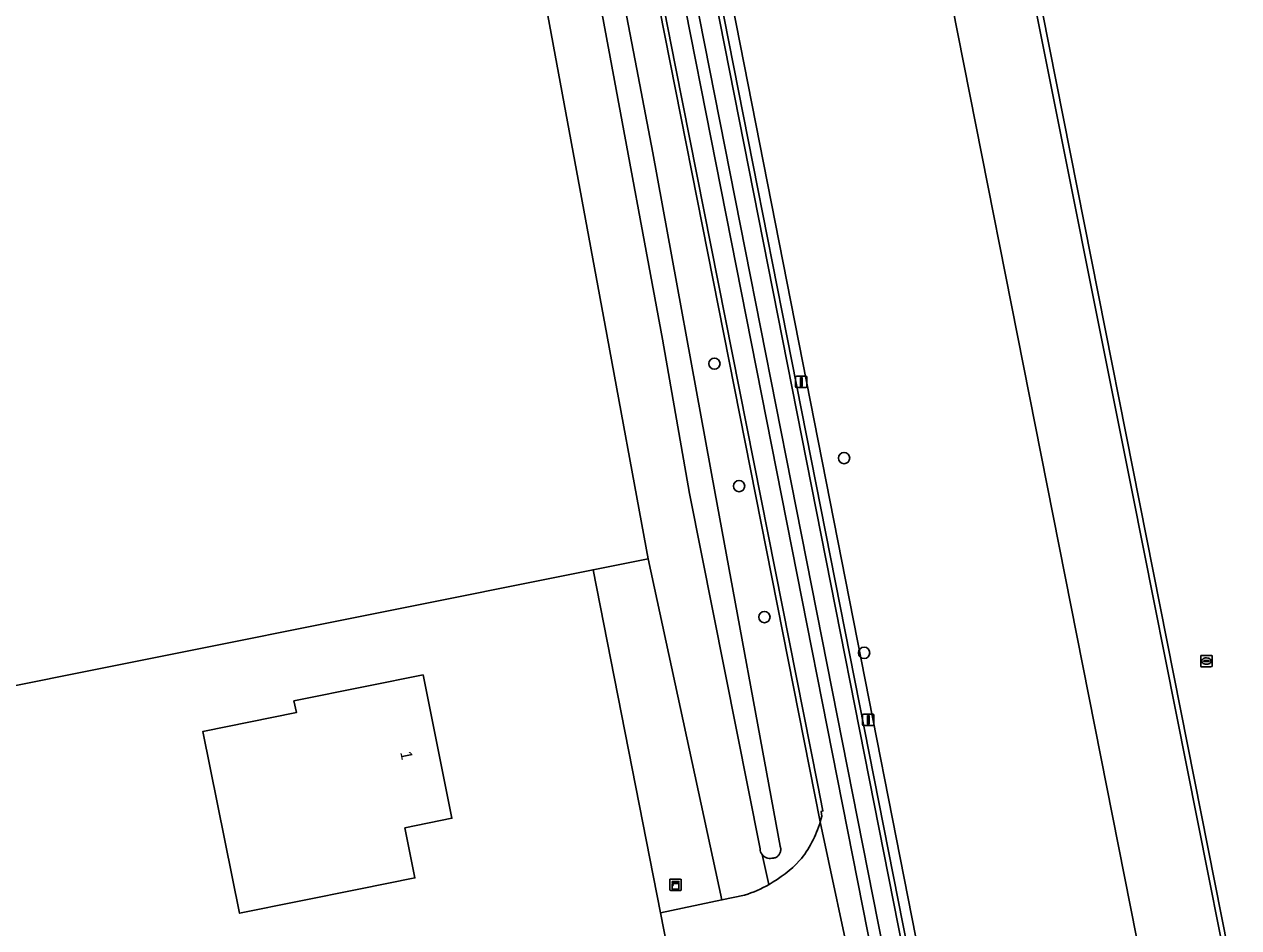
# Model space of a CAD drawing. Extents: x 160203 to 161530, y 379528 to 381797.
# Drawn here: x 160889.3 to 160995.1, y 379712.2 to 379790.9 of the extents above; entities that cross this region are included whole.
import ezdxf

# ---------------------------------------------------------------- set-up
doc = ezdxf.new("R2010")
doc.units = 0
for name, color, linetype in [('IMGEO_Berm_groen', 7, 'Continuous'), ('IMGEO_Berm_open', 7, 'Continuous'), ('IMGEO_Boom', 7, 'Continuous'), ('IMGEO_Erf', 7, 'Continuous'), ('IMGEO_Grasland_overig', 7, 'Continuous'), ('IMGEO_Groenvoorziening', 7, 'Continuous'), ('IMGEO_Hek', 7, 'Continuous'), ('IMGEO_Kast', 7, 'Continuous'), ('IMGEO_Lichtmast', 7, 'Continuous'), ('IMGEO_Loofbos', 7, 'Continuous'), ('IMGEO_Pand', 7, 'Continuous'), ('IMGEO_Pand_nummerreeks', 7, 'Continuous'), ('IMGEO_Rijbaan_lokaal_gesloten', 7, 'Continuous'), ('IMGEO_Rijbaan_lokaal_open', 7, 'Continuous'), ('IMGEO_Waterleidingput', 7, 'Continuous'), ('IMGEO_Waterloop', 7, 'Continuous')]:
    doc.layers.add(name, color=color, linetype=linetype)

msp = doc.modelspace()

# ---------------------------------------------------------------- linework, layer by layer
at = {"layer": 'IMGEO_Berm_groen'}
for points in [[(160958.63, 379721.42), (160935.77, 379837.08), (160928.05, 379876.62)], [(160928.2, 379862.18), (160942.76, 379786.36), (160944.04, 379779.68), (160949.49, 379750), (160955.13, 379719.31), (160955.14, 379719.29), (160955.16, 379719.23), (160955.18, 379719.16), (160955.19, 379719.09), (160955.19, 379719.03), (160955.19, 379718.96), (160955.18, 379718.89), (160955.17, 379718.82), (160955.15, 379718.76), (160955.12, 379718.7), (160955.09, 379718.64), (160955.06, 379718.58), (160955.02, 379718.53), (160954.97, 379718.48), (160954.92, 379718.43), (160954.87, 379718.39), (160954.81, 379718.35), (160954.75, 379718.32), (160954.69, 379718.3), (160954.62, 379718.28), (160954.56, 379718.27), (160954.49, 379718.26), (160954.42, 379718.26)], [(160953.56, 379718.57), (160954.16, 379715.97)]]:
    msp.add_lwpolyline(points, dxfattribs=at)
for centre, radius, start, end in [((160949.5, 379724.12), 9.52, 320.3484, 343.5664), ((160954.24, 379719.08), 0.848, 216.9975, 282.3736), ((160948.64, 379725.84), 11.31, 299.2453, 316.4214)]:
    msp.add_arc(centre, radius, start, end, dxfattribs=at)
at = {"layer": 'IMGEO_Berm_open'}
for points in [[(160977.01, 379644.98), (160931.19, 379877.16)], [(160930.17, 379876.91), (160975.99, 379644.84)]]:
    msp.add_lwpolyline(points, dxfattribs=at)
at = {"layer": 'IMGEO_Boom'}
for centre in [(160949.41, 379761.32), (160960.7, 379753.1), (160951.56, 379750.66), (160953.77, 379739.25), (160962.45, 379736.14)]:
    msp.add_circle(centre, 0.489, dxfattribs=at)
at = {"layer": 'IMGEO_Erf'}
for points in [[(160945.57, 379709.21), (160944.72, 379713.51), (160938.84, 379743.37), (160882.02, 379731.98), (160889.82, 379690.64), (160946.9, 379702.08)], [(160918.44, 379715.55), (160908.07, 379713.46), (160904.87, 379729.29), (160913.01, 379730.93), (160912.8, 379731.95), (160919.14, 379733.23), (160924.04, 379734.22), (160926.56, 379721.73), (160922.46, 379720.9), (160923.34, 379716.54)]]:
    msp.add_lwpolyline(points, close=True, dxfattribs=at)
at = {"layer": 'IMGEO_Grasland_overig'}
msp.add_lwpolyline([(161089.29, 379874.82), (161088.06, 379883.66), (161097.99, 379885.6), (161095.06, 379898.6), (161067.76, 379903.29), (161066.72, 379897.25), (161064.96, 379897.55), (161064.27, 379901.09), (161048.67, 379898.05), (161049.44, 379894.12), (161037.66, 379891.83), (161037.23, 379894.01), (161021.55, 379891.08), (161008.69, 379888.67), (161005.82, 379890.02), (161000, 379888.88), (160960.29, 379881.14), (160984.65, 379758.21), (161001.9, 379671.16), (161088.81, 379688.39), (161124.8, 379695.53), (161114.01, 379750)], close=True, dxfattribs=at)
msp.add_lwpolyline([(160840.36, 379818.7), (160816.73, 379790.12), (160856.72, 379758.62), (160866.07, 379730.92), (160881.55, 379684.93), (160889.82, 379690.64), (160882.02, 379731.98), (160938.84, 379743.37), (160943.64, 379744.33), (160939.89, 379764.64), (160934.91, 379791.64)], dxfattribs=at)
at = {"layer": 'IMGEO_Groenvoorziening'}
for points in [[(161124.8, 379695.53), (161088.81, 379688.39), (161001.9, 379671.16), (160984.65, 379758.21), (160960.29, 379881.14), (160959.82, 379881.05), (160959.92, 379880.51), (160960.04, 379879.9), (160973.15, 379813.39), (160984.11, 379758.57), (160985.83, 379750), (161000, 379678.61), (161001.69, 379670.67), (161089.34, 379688.04), (161125.46, 379695.28), (161122.82, 379708.52), (161121.99, 379712.67), (161114.55, 379750), (161114.01, 379750)], [(160933, 379878.98), (160975.52, 379663.39), (160976.37, 379663.39), (160974.15, 379674.69), (160974.08, 379675.03), (160933.99, 379879.07)]]:
    msp.add_lwpolyline(points, close=True, dxfattribs=at)
for points in [[(160933.99, 379879.07), (160974.08, 379675.03), (160974.15, 379674.69), (160976.37, 379663.39), (161000.99, 379663.16), (161006.45, 379663.11), (161063.74, 379662.75)], [(161142.92, 379692.64), (161145.98, 379696.54), (161138.27, 379693.24), (161136.23, 379692.23), (161130.68, 379689.47), (161118.14, 379687.03), (161106.5, 379683.85), (161096.48, 379679.04), (161085.04, 379672.67), (161070.4, 379668.01), (161059.14, 379666.39), (161049.4, 379665.53), (161034.57, 379663.65), (161025.83, 379663.99), (161019.86, 379665.34), (161017.76, 379665.27), (161013.76, 379664.34), (161011.91, 379663.38), (161000.99, 379663.27), (160995.51, 379665.23), (160994.95, 379666.91), (160953.02, 379879)]]:
    msp.add_lwpolyline(points, dxfattribs=at)
at = {"layer": 'IMGEO_Hek'}
for points in [[(160960.04, 379879.9), (160973.15, 379813.39), (160984.11, 379758.57)], [(160934.91, 379791.64), (160939.89, 379764.64)], [(160939.89, 379764.64), (160943.64, 379744.33)], [(160984.11, 379758.57), (160985.83, 379750)], [(161000, 379678.61), (160985.83, 379750)], [(160943.64, 379744.33), (160938.84, 379743.37)], [(160889.82, 379690.64), (160882.02, 379731.98), (160938.84, 379743.37)], [(160938.84, 379743.37), (160944.72, 379713.51)], [(160944.72, 379713.51), (160945.57, 379709.21)]]:
    msp.add_lwpolyline(points, dxfattribs=at)
at = {"layer": 'IMGEO_Kast'}
for p, q in [((160945.53, 379715.52), (160945.53, 379716.36)), ((160945.53, 379716.36), (160945.53, 379715.52)), ((160945.6, 379716.44), (160946.44, 379716.44)), ((160946.44, 379716.44), (160945.6, 379716.44)), ((160946.52, 379716.37), (160946.52, 379715.53)), ((160946.52, 379715.53), (160946.52, 379716.37)), ((160946.45, 379715.44), (160945.61, 379715.44)), ((160945.61, 379715.44), (160946.45, 379715.44))]:
    msp.add_line(p, q, dxfattribs=at)
for points in [[(160945.72, 379716.23), (160946.32, 379716.23), (160946.32, 379716.15), (160945.72, 379716.15), (160945.72, 379716.23)], [(160945.72, 379716.06), (160946.32, 379716.06), (160946.32, 379715.57), (160945.72, 379715.57), (160945.72, 379716.06)]]:
    msp.add_lwpolyline(points, dxfattribs=at)
msp.add_circle((160945.8, 379715.91), 0.0377, dxfattribs=at)
for centre, start, end in [((160945.6, 379716.37), 92.4484, 184.2845), ((160945.6, 379716.37), 92.4484, 184.2845), ((160946.45, 379716.37), 2.4484, 94.2845), ((160946.45, 379716.37), 2.4484, 94.2845), ((160945.6, 379715.52), 182.4484, 274.2845), ((160945.6, 379715.52), 182.4484, 274.2845), ((160946.45, 379715.52), 272.4484, 4.2845), ((160946.45, 379715.52), 272.4484, 4.2845)]:
    msp.add_arc(centre, 0.0779, start, end, dxfattribs=at)
at = {"layer": 'IMGEO_Lichtmast'}
for p, q in [((160956.48, 379759.33), (160956.48, 379760.13)), ((160956.48, 379760.13), (160956.48, 379759.33)), ((160956.58, 379760.23), (160957.37, 379760.23)), ((160957.37, 379760.23), (160956.58, 379760.23)), ((160957.47, 379760.13), (160957.47, 379759.33)), ((160957.47, 379759.33), (160957.47, 379760.13)), ((160957.37, 379759.23), (160956.58, 379759.23)), ((160956.58, 379759.23), (160957.37, 379759.23)), ((160962.31, 379729.91), (160962.31, 379730.71)), ((160962.31, 379730.71), (160962.31, 379729.91)), ((160962.41, 379730.81), (160963.2, 379730.81)), ((160963.2, 379730.81), (160962.41, 379730.81)), ((160963.3, 379730.71), (160963.3, 379729.91)), ((160963.3, 379729.91), (160963.3, 379730.71)), ((160963.2, 379729.81), (160962.41, 379729.81)), ((160962.41, 379729.81), (160963.2, 379729.81))]:
    msp.add_line(p, q, dxfattribs=at)
for points in [[(160956.9, 379760.11), (160957.05, 379760.11), (160957.05, 379759.36), (160956.9, 379759.36), (160956.9, 379760.11)], [(160962.73, 379730.68), (160962.88, 379730.68), (160962.88, 379729.93), (160962.73, 379729.93), (160962.73, 379730.68)]]:
    msp.add_lwpolyline(points, dxfattribs=at)
for centre, start, end in [((160956.58, 379760.13), 90, 180), ((160956.58, 379760.13), 90, 180), ((160957.37, 379760.13), 0, 90), ((160957.37, 379760.13), 360, 90), ((160956.58, 379759.33), 180, 270), ((160956.58, 379759.33), 180, 270), ((160957.37, 379759.33), 270, 0), ((160957.37, 379759.33), 270, 0), ((160962.41, 379730.71), 90, 180), ((160962.41, 379730.71), 90, 180), ((160963.2, 379730.71), 0, 90), ((160963.2, 379730.71), 360, 90), ((160962.41, 379729.91), 180, 270), ((160962.41, 379729.91), 180, 270), ((160963.2, 379729.91), 270, 0), ((160963.2, 379729.91), 270, 0)]:
    msp.add_arc(centre, 0.1, start, end, dxfattribs=at)
at = {"layer": 'IMGEO_Loofbos'}
for points in [[(160953.02, 379879), (160994.95, 379666.91), (160995.51, 379665.23)], [(160922.21, 379877.28), (160919.54, 379875.8), (160921.7, 379863.36), (160934.91, 379791.64), (160939.89, 379764.64), (160943.64, 379744.33), (160950.07, 379714.63), (160952.04, 379715.05)], [(160953.39, 379719.07), (160947.23, 379750), (160944.89, 379763.46), (160940.33, 379788), (160932.36, 379830.88)], [(161000, 379678.61), (160985.83, 379750), (160984.11, 379758.57), (160973.15, 379813.39)], [(160954.16, 379715.97), (160953.56, 379718.57)]]:
    msp.add_lwpolyline(points, dxfattribs=at)
msp.add_lwpolyline([(160950.07, 379714.63), (160943.64, 379744.33), (160938.84, 379743.37), (160944.72, 379713.51)], close=True, dxfattribs=at)
for centre, radius, start, end in [((160954.24, 379719.09), 0.852, 181.2587, 217.0634), ((160948.63, 379725.84), 11.32, 287.5566, 299.2704)]:
    msp.add_arc(centre, radius, start, end, dxfattribs=at)
at = {"layer": 'IMGEO_Pand'}
msp.add_lwpolyline([(160918.44, 379715.55), (160923.34, 379716.54), (160922.46, 379720.9), (160926.56, 379721.73), (160924.04, 379734.22), (160919.14, 379733.23), (160912.8, 379731.95), (160913.01, 379730.93), (160904.87, 379729.29), (160908.07, 379713.46)], close=True, dxfattribs=at)
at = {"layer": 'IMGEO_Rijbaan_lokaal_gesloten'}
for points in [[(160975.92, 379659.23), (160975.09, 379663.4), (160924.29, 379920.91)], [(160931.19, 379877.16), (160977.01, 379644.98)], [(160928.42, 379876.71), (160946.01, 379787.18), (160958.42, 379724.61), (160958.86, 379722.38), (160958.7, 379722.31), (160958.76, 379721.91), (160958.63, 379721.42), (160961.6, 379707.42), (160961.94, 379706.57), (160974.23, 379644.48)], [(160975.99, 379644.84), (160930.17, 379876.91)]]:
    msp.add_lwpolyline(points, dxfattribs=at)
at = {"layer": 'IMGEO_Rijbaan_lokaal_open'}
for points in [[(160924.7, 379921.2), (160923.56, 379926.8), (160923.14, 379926.74), (160924.29, 379920.91), (160975.09, 379663.4), (160975.52, 379663.39), (160933, 379878.98), (160932.65, 379880.98), (160932.53, 379881.6), (160924.74, 379920.98)], [(160928.42, 379876.71), (160928.17, 379876.68), (160928.05, 379876.62), (160935.77, 379837.08), (160958.63, 379721.42), (160958.76, 379721.91), (160958.7, 379722.31), (160958.86, 379722.38), (160958.42, 379724.61), (160946.01, 379787.18)]]:
    msp.add_lwpolyline(points, close=True, dxfattribs=at)
for points in [[(160961.6, 379707.42), (160958.63, 379721.42)], [(160952.04, 379715.05), (160950.07, 379714.63), (160944.72, 379713.51), (160945.57, 379709.21), (160950.95, 379710.23), (160954.03, 379710.81)]]:
    msp.add_lwpolyline(points, dxfattribs=at)
for centre, radius, start, end in [((160949.5, 379724.12), 9.52, 320.3484, 343.5664), ((160948.64, 379725.84), 11.31, 299.2453, 316.4214), ((160948.63, 379725.84), 11.32, 287.5566, 299.2704)]:
    msp.add_arc(centre, radius, start, end, dxfattribs=at)
at = {"layer": 'IMGEO_Waterleidingput'}
for p, q in [((160991.76, 379734.99), (160991.76, 379735.85)), ((160991.83, 379735.92), (160992.68, 379735.92)), ((160992.02, 379735.41), (160992.02, 379735.43)), ((160992.06, 379735.46), (160992.46, 379735.46)), ((160992.45, 379735.38), (160992.06, 379735.38)), ((160992.25, 379735.7), (160992.27, 379735.7)), ((160992.5, 379735.43), (160992.5, 379735.41)), ((160992.76, 379735.85), (160992.76, 379734.99)), ((160992.68, 379734.92), (160991.83, 379734.92)), ((160992.27, 379735.14), (160992.24, 379735.14))]:
    msp.add_line(p, q, dxfattribs=at)
for points in [[(160991.76, 379734.99), (160991.76, 379735.85)], [(160991.83, 379735.92), (160992.68, 379735.92)], [(160992.76, 379735.85), (160992.76, 379734.99)], [(160992.68, 379734.92), (160991.83, 379734.92)]]:
    msp.add_lwpolyline(points, dxfattribs=at)
for centre, radius, start, end in [((160991.83, 379735.84), 0.0765, 91.552, 178.448), ((160991.83, 379735.84), 0.0765, 91.552, 178.448), ((160992.06, 379735.42), 0.0403, 85.8775, 175.7526), ((160992.05, 379735.41), 0.0366, 178.938, 274.7102), ((160992.46, 379735.42), 0.043, 264.8664, 352.4533), ((160992.46, 379735.42), 0.0386, 1.7309, 96.639), ((160992.68, 379735.84), 0.0765, 1.552, 88.448), ((160992.68, 379735.84), 0.0765, 1.552, 88.448), ((160991.83, 379735), 0.0765, 181.552, 268.448), ((160991.83, 379735), 0.0765, 181.552, 268.448), ((160992.68, 379735), 0.0765, 271.552, 358.448), ((160992.68, 379735), 0.0765, 271.552, 358.448)]:
    msp.add_arc(centre, radius, start, end, dxfattribs=at)
for centre, major_axis, ratio, start_param, end_param in [((160992.24, 379735.42), (-0.387, 0.002), 0.722429, 4.712389, 7.853982), ((160992.27, 379735.42), (-0.39, 0.002), 0.717154, 1.570796, 4.712389)]:
    msp.add_ellipse(centre, major_axis=major_axis, ratio=ratio, start_param=start_param, end_param=end_param, dxfattribs=at)
at = {"layer": 'IMGEO_Waterloop'}
for points in [[(160954.42, 379718.26), (160954.49, 379718.26), (160954.56, 379718.27), (160954.62, 379718.28), (160954.69, 379718.3), (160954.75, 379718.32), (160954.81, 379718.35), (160954.87, 379718.39), (160954.92, 379718.43), (160954.97, 379718.48), (160955.02, 379718.53), (160955.06, 379718.58), (160955.09, 379718.64), (160955.12, 379718.7), (160955.15, 379718.76), (160955.17, 379718.82), (160955.18, 379718.89), (160955.19, 379718.96), (160955.19, 379719.03), (160955.19, 379719.09), (160955.18, 379719.16), (160955.16, 379719.23), (160955.14, 379719.29), (160955.13, 379719.31), (160949.49, 379750), (160944.04, 379779.68), (160942.76, 379786.36), (160928.2, 379862.18)], [(160932.36, 379830.88), (160940.33, 379788), (160944.89, 379763.46), (160947.23, 379750), (160953.39, 379719.07)]]:
    msp.add_lwpolyline(points, dxfattribs=at)
for centre, radius, start, end in [((160954.24, 379719.09), 0.852, 181.2587, 217.0634), ((160954.24, 379719.08), 0.848, 216.9975, 282.3736)]:
    msp.add_arc(centre, radius, start, end, dxfattribs=at)

# ---------------------------------------------------------------- texts
at = {"layer": 'IMGEO_Pand_nummerreeks'}
msp.add_text('1', height=1, rotation=281.4236, dxfattribs=at).set_placement((160922.05, 379727.48))

doc.saveas('drawing.dxf')
